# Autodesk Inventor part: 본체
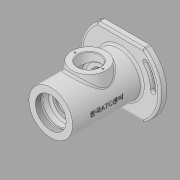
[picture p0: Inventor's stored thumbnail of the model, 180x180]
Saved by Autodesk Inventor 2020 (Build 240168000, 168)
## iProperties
Created: 2022-05
Part Number: 본체
Material: 일반
Document SubType Name: Modeling
Designer: User
Density: 1 g/cm^3
Appearance: 기본값
Author: User
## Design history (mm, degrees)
sketch "스케치1"
  geometry: L1 (-125, -47)-(125, -47); L2 (125, -47)-(125, 47); L3 (125, 47)-(-125, 47); L4 (-125, 47)-(-125, -47); L5 (-125, -47)-(125, 47); L6 (125, -47)-(-125, 47); C1 r 58 at (0, 0); 5 further points
  constraints: 12 end point, 2 midpoint, 2 parallel, 1 centre point, 1 coincident, 1 horizontal, 1 perpendicular
  dimensions: "d0" = 116 diameter of C1; "d1" = 94 distance between parallel lines of L1 L3; "d2" = 250 distance between parallel lines of L4 L2
extrude "돌출1" new body sketch "스케치1" distance "d3" = 10; taper "d4" = 0 deg
sketch "스케치3"
  geometry: C1 r 36 at (0, 0); 1 further point
  constraints: 1 centre point, 1 coincident
  dimensions: "d5" = 72 diameter of C1
extrude "돌출2" join sketch "스케치3" distance "d6" = 3; taper "d7" = 0 deg
sketch "스케치4"
  geometry: L1 (-36, -3)-(36, -3) reference; L2 (0, -3)-(-32, -3); L3 (-32, -3)-(-32, 112); L4 (-32, 112)-(0, 112); L5 (0, 112)-(0, -3); L6 (-22.5, 112)-(-22.5, 104); L7 (-22.5, 104)-(-24, 104); L8 (-24, 104)-(-24, 101); L9 (-24, 101)-(-22.5, 101); L10 (-22.5, 101)-(-22.5, 90); L11 (-22.5, 90)-(-17.5, 90); L12 (-17.5, 90)-(-17.5, 87.75); L13 (-17.5, 87.75)-(-18.5, 87.75); L14 (-18.5, 87.75)-(-18.5, 86); L15 (-18.5, 86)-(-17.5, 86); L16 (-17.5, 86)-(-17.5, 75); L17 (-17.5, 75)-(-27, 75); L18 (-27, 75)-(-27, 37); L19 (-27, 37)-(-17.5, 37); L20 (-17.5, 37)-(-17.5, 26); L21 (-17.5, 26)-(-15, 26); L22 (-15, 26)-(-15, 21); L23 (-15, 21)-(-11, 21); L24 (-11, 21)-(-11, 18.3); L25 (-11, 18.3)-(-15, 18.3); L26 (-15, 18.3)-(-15, 11); L27 (-15, 11)-(-20, 11); L28 (-20, 11)-(-30, -3); 3 further points
  constraints: 54 end point, 18 perpendicular, 5 point on line, 3 parallel, 3 vertical, 1 horizontal, 1 midpoint
  dimensions: "d8" = 115 distance of L2.end L3.end; "d9" = 64 diameter of L3 L5; "d10" = 48 diameter of L8 L5; "d11" = 45 diameter of L10 L5; "d12" = 45 diameter of L6 L5; "d13" = 37 diameter of L14 L5; "d14" = 35 diameter of L12 L5; "d15" = 54 diameter of L18 L5; "d16" = 30 diameter of L22 L5; "d17" = 22 diameter of L24 L5; "d18" = 30 diameter of L26 L5; "d19" = 60 diameter of L28.end L5; "d20" = 8 distance of L6.start L6.end; "d21" = 3 distance of L7.end L8.end; "d22" = 22 distance between parallel lines of L11 L4; "d23" = 1.75 distance of L13.end L14.end; "d24" = 4 distance between parallel lines of L15 L11; "d25" = 11 distance from line of L17 L15.end; "d26" = 38 distance between parallel lines of L19 L17; "d27" = 11 distance between parallel lines of L21 L19; "d28" = 5 distance between parallel lines of L23 L21; "d29" = 14 distance between parallel lines of L2 L27; "d30" = 7.3 distance between parallel lines of L25 L27; "d31" = 40 diameter of L27.end L5
revolve "회전1" stored, may be unused: angle "d32" = 90 deg
revolve "회전2" stored, may be unused: angle "d33" = 90 deg
node "작업 평면1"
sketch "스케치5"
  geometry: L1 (32, 112)-(-32, 112) reference; L2 (-33.985, 0)-(33.985, 0) reference; C1 r 25 at (0, 56); 2 further points
  constraints: 1 centre point, 1 midpoint, 1 vertical alignment
  dimensions: "d35" = 56 distance from line of C1.centre L1; "d36" = 50 diameter of C1
extrude "돌출3" join sketch "스케치5" stored distance "d37" = 3; taper "d38" = 5 deg
sketch "스케치6"
  geometry: C1 r 25 at (0, 0) reference; 2 further points
  constraints: 1 coincident
hole "구멍1" sketch "스케치6" at (0, 0) diameter "d39" = 32; stored, may be unused: countersink angle "d43" = 90 deg, drill point angle "d45" = 118 deg; dims "d40" = 6, "d41" = 12, "d42" = 5, "d44" = 8
fillet "모깎기1" dims "d46" = 3
sketch "스케치8"
  geometry: L1 (0, 0)-(20.5, 0); C1 r 25 at (0, 0) reference; 2 further points
  constraints: 2 end point, 1 coincident, 1 horizontal
  dimensions: "d48" = 20.5 distance of L1.start L1.end
hole "구멍2" sketch "스케치8" at (20.5, 0) diameter "d49" = 2.459; stored, may be unused: countersink angle "d53" = 90 deg, drill point angle "d55" = 118 deg; dims "d50" = 6, "d51" = 12, "d52" = 5, "d54" = 8
sketch "스케치9" dims "d60" = 96
  geometry: L1 (48, 0)-(0, 0); L2 (0, 0)-(36.77, -30.854); L3 (0, 0)-(-36.77, 30.854); A1 r 48 centre (0, 0) between (36.77, -30.854) and (48, 0); A2 r 52 centre (0, 0) between (39.834, -33.425) and (52, 0); A3 r 44 centre (0, 0) between (33.706, -28.283) and (44, 0); A4 r 4 centre (36.77, -30.854) between (33.706, -28.283) and (39.834, -33.425); A5 r 4 centre (48, 0) between (52, 0) and (44, 0); A6 r 4 centre (-36.77, 30.854) between (-33.706, 28.283) and (-39.834, 33.425); A7 r 52 centre (0, 0) between (-39.834, 33.425) and (-52, 0); A8 r 44 centre (0, 0) between (-33.706, 28.283) and (-44, 0); A9 r 4 centre (-48, 0) between (-52, 0) and (-44, 0); 2 further points
  constraints: 18 point on circle, 9 centre point, 6 end point, 4 tangent, 2 coincident, 1 horizontal, 29 other
  dimensions: "d67" = 4 radius of A4; "d68" = 40 deg angle of L1 L2; "d71" = 360 deg dimension on point (0, 0) L2.end (derived)
extrude "돌출4" cut sketch "스케치9" distance "d73" = 4.4; taper "d74" = 0 deg
sketch "스케치10"
  geometry: A1 r 4 centre (36.77, -30.854) between (33.706, -28.283) and (39.834, -33.425) reference; A2 r 44 centre (0, 0) between (33.706, -28.283) and (44, 0) reference; A3 r 4 centre (48, 0) between (52, 0) and (44, 0) reference; A4 r 52 centre (0, 0) between (39.834, -33.425) and (52, 0) reference; A5 r 44 centre (0, 0) between (-33.706, 28.283) and (-44, 0) reference; A6 r 4 centre (-48, 0) between (-52, 0) and (-44, 0) reference; A7 r 52 centre (0, 0) between (-39.834, 33.425) and (-52, 0) reference; A8 r 4 centre (-36.77, 30.854) between (-33.706, 28.283) and (-39.834, 33.425) reference; A9 r 48 centre (0, 0) between (36.77, -30.854) and (48, 0); A10 r 50.25 centre (0, 0) between (38.494, -32.3) and (50.25, 0); A11 r 45.75 centre (0, 0) between (35.047, -29.408) and (45.75, 0); A12 r 2.25 centre (36.77, -30.854) between (35.047, -29.408) and (38.494, -32.3); A13 r 2.25 centre (48, 0) between (50.25, 0) and (45.75, 0); A14 r 48 centre (0, 0) between (-36.77, 30.854) and (-48, 0); A15 r 50.25 centre (0, 0) between (-38.494, 32.3) and (-50.25, 0); A16 r 45.75 centre (0, 0) between (-35.047, 29.408) and (-45.75, 0); A17 r 2.25 centre (-36.77, 30.854) between (-35.047, 29.408) and (-38.494, 32.3); A18 r 2.25 centre (-48, 0) between (-50.25, 0) and (-45.75, 0); 1 further point
  constraints: 20 point on circle, 10 centre point, 8 tangent, 2 coincident
  dimensions: "d75" = 4.5 diameter of A13; "d76" = 4.5 diameter of A17
extrude "돌출5" cut sketch "스케치10" extent not by distance; stored distance "d77" = 0; taper "d78" = 0 deg
sketch "스케치11"
  geometry: C1 r 4 at (36.77, 30.854); C2 r 4 at (-36.77, -30.854); A1 r 4 centre (-36.77, -30.854) between (-39.834, -33.425) and (-33.706, -28.283) reference; A2 r 4 centre (36.77, 30.854) between (39.834, 33.425) and (33.706, 28.283) reference; 5 further points
  constraints: 2 centre point, 2 coincident
  dimensions: "d79" = 8 diameter of C1; "d80" = 8 diameter of C2
extrude "돌출6" cut sketch "스케치11" extent not by distance; stored distance "d81" = 0; taper "d82" = 0 deg
fillet "모깎기2" dims "d83" = 3
fillet "모깎기3" dims "d84" = 3
fillet "모깎기4" dims "d85" = 3
feature "스레드1" dims "d86" = 8, "d87" = 0
fillet "모깎기5" dims "d88" = 3
chamfer "모따기1" distance "d89" = 1; stored, may be unused: second distance "d90" = 2, angle "d91" = 45 deg
chamfer "모따기2" distance "d92" = 1; stored, may be unused: second distance "d93" = 2, angle "d94" = 45 deg
chamfer "모따기3" distance "d95" = 1; stored, may be unused: second distance "d96" = 2, angle "d97" = 45 deg
fillet "모깎기6" dims "d98" = 3
fillet "모깎기7" dims "d99" = 0.6, "d100" = 0.5
fillet "모깎기8" dims "d101" = 3
chamfer "모따기4" distance "d102" = 0.7; stored, may be unused: second distance "d103" = 2, angle "d104" = 30 deg
fillet "모깎기9" dims "d105" = 3
chamfer "모따기5" distance "d106" = 1; stored, may be unused: second distance "d107" = 2, angle "d108" = 30 deg
node "작업 평면3"
sketch "스케치12"
  geometry: L1 (3.602, 86.887)-(3.602, 37.113); L2 (3.602, 37.113)-(-3.602, 37.113); L3 (-3.602, 37.113)-(-3.602, 86.887); L4 (-3.602, 86.887)-(3.602, 86.887); L5 (3.602, 86.887)-(-3.602, 37.113); L6 (46.4, 0)-(-46.4, 0) reference; 2 further points
  constraints: 2 end point, 1 midpoint, 1 vertical alignment, 2 other
  dimensions: "d110" = 62 distance from line of point (0, 62) L6
feature "엠보싱1" sketch "스케치12" dims "d8" = 115, "d9" = 64, "d10" = 48, "d11" = 45, "d12" = 45, "d13" = 37, "d14" = 35, "d15" = 54, "d16" = 30, "d17" = 22, "d18" = 30, "d19" = 60, "d20" = 8, "d21" = 3, "d22" = 22, "d23" = 1.75, "d24" = 4, "d25" = 11, "d26" = 38, "d27" = 11, "d28" = 5, "d29" = 14, "d30" = 7.3, "d31" = 40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
node "솔리드1"
pattern_circular "원형 패턴1" dims angle "d57" = 360 deg
node "투영된 루프1"
node "투영된 루프2"
feature "A9D066F2-1C7D-4E18-AEED-F7BC21143FA4" dims "d86" = 8, "d87" = 0
other parameters: "d34" = -38, "d109" = -32.5
